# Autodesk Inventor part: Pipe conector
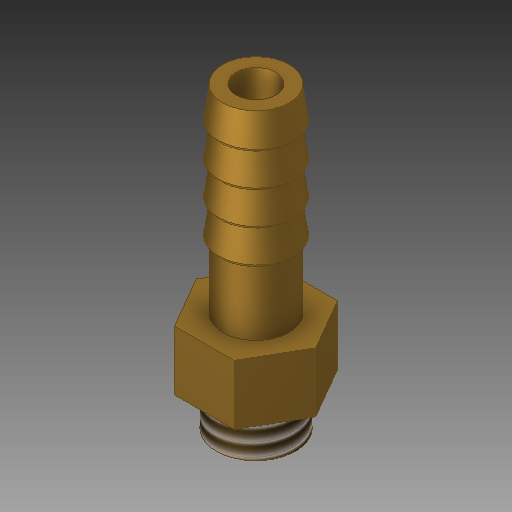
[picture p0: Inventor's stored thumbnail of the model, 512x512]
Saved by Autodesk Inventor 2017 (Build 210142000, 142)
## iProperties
Created: 2020-03
Part Number: Pipe conector
Material: Brass, Soft Yellow
Document SubType Name: Modeling
Designer: user
Density: 8.47 g/cm^3
Appearance: Brass - Satin
Mass: 4.10205 g
Surface Area: 7.43202 cm^2
Volume: 0.484303 cm^3
Author: user
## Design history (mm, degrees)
sketch "Sketch1"
  geometry: C1 r 1.5 at (0, 0); C2 r 3 at (0, 0); 1 further point
  constraints: 2 centre point, 2 coincident
  dimensions: "d0" = 3 diameter of C1; "d1" = 6 diameter of C2
extrude "Extrusion1" new body sketch "Sketch1" distance "d2" = 3; taper "d3" = 0 deg
sketch "Sketch2"
  geometry: L1 (-4.5, 0)-(-2.25, 3.897); L2 (-2.25, 3.897)-(2.25, 3.897); L3 (2.25, 3.897)-(4.5, 0); L4 (4.5, 0)-(2.25, -3.897); L5 (2.25, -3.897)-(-2.25, -3.897); L6 (-2.25, -3.897)-(-4.5, 0); 2 further points
  constraints: 12 end point, 1 coincident, 13 other
  dimensions: "d4" = 9 distance of L3.end L1.start
extrude "Extrusion2" join sketch "Sketch2" distance "d5" = 4.5; taper "d6" = 0 deg
sketch "Sketch3"
  geometry: C1 r 1.5 at (0, 0); 1 further point
  constraints: 1 centre point, 1 coincident
extrude "Extrusion3" cut sketch "Sketch3" distance "d7" = 4.5; taper "d8" = 0 deg
sketch "Sketch5"
  geometry: L1 (7.5, 1.5)-(7.5, -1.5) reference; L2 (7.5, 1.5)-(22.5, 1.5); L3 (22.5, 1.5)-(22.5, 2.5); L4 (22.5, 2.5)-(20.189, 2.812); L5 (19.964, 2.64)-(19.945, 2.5); L6 (19.945, 2.5)-(17.663, 2.808); L7 (17.436, 2.61)-(17.436, 2.5); L8 (17.436, 2.5)-(15.154, 2.808); L9 (14.927, 2.5)-(14.927, 2.61); L10 (14.927, 2.5)-(12.645, 2.808); L11 (12.418, 2.61)-(12.418, 2.5); L12 (12.418, 2.5)-(7.5, 2.5); L13 (7.5, 0)-(7.5, 3.897) reference; L14 (7.5, 2.5)-(7.5, 1.5); L15 (-4.5, 0)-(27, 0) reference; A1 r 0.2 centre (20.162, 2.614) between (20.189, 2.812) and (19.964, 2.64); A2 r 0.2 centre (17.636, 2.61) between (17.663, 2.808) and (17.436, 2.61); A3 r 0.2 centre (15.127, 2.61) between (15.154, 2.808) and (14.927, 2.61); A4 r 0.2 centre (12.618, 2.61) between (12.645, 2.808) and (12.418, 2.61); 1 further point
  constraints: 24 end point, 8 point on circle, 8 tangent, 4 centre point, 3 equal radius, 3 parallel, 3 vertical, 2 perpendicular, 1 collinear, 1 horizontal, 1 point on line
  dimensions: "d9" = 15 distance of L1.start L2.end; "d10" = 1 distance of L2.end L3.end; "d11" = 0.2 radius of A1
revolve "Revolution1" sketch "Sketch5" stored, may be unused: angle "d12" = 90 deg
thread "Thread1" dims "d13" = 10, "d14" = 0
body "Solid1"
